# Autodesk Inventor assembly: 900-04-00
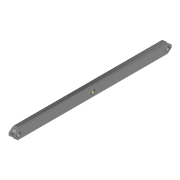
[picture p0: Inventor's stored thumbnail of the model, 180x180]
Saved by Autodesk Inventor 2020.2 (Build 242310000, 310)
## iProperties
Created: 2015-10
Part Number: 900-04-00
Document SubType Name: Konstrukcja spawana
Designer: F.Stasiak
Weld Material: Aluminium 6061, spawane
Mass: 21817.1 g
Surface Area: 11771.4 cm^2
Volume: 2908.78 cm^3
Density: 7.50043 g/cm^3
Catalog Web Link: www.expertbooks.pl
Manager: www.cadconsulting.pl
Company: Fabian Stasiak CAD Consulting
Author: F.Stasiak
Subject: Zbiór ćwiczeń. Autodesk Inventor 2020. Kurs Professional
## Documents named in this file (3)
- C:\2020_Kurs_Professional\R3 Dynamika\Komponenty_dyn\900-04-00.iam
- C:\2020_Kurs_Professional\R3 Dynamika\Komponenty_dyn\DIN 59 410 - 900-04-01.ipt
- C:\2020_Kurs_Professional\R3 Dynamika\Komponenty_dyn\900-03-02.ipt
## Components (4 placed, 2 different names)
1. DIN 59 410 - 900-04-01:1 — Zestawiający:1, Zestawiający:2, Zestawiający:3, Zestawiający:4, Zestawiający:5, Zestawiający:6
2. 900-03-02:1 — Zestawiający:1, Zestawiający:2, Zestawiający:8
3. 900-03-02:2 — Zestawiający:3, Zestawiający:4, Zestawiający:7, Zestawiający:8
4. 900-03-02:3 — Zestawiający:5, Zestawiający:6, Zestawiający:7
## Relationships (8: Mate 8)
- Zestawiający:1 [Mate]: DIN 59 410 - 900-04-01:1 ↔ 900-03-02:1
- Zestawiający:2 [Mate]: DIN 59 410 - 900-04-01:1 ↔ 900-03-02:1
- Zestawiający:3 [Mate]: DIN 59 410 - 900-04-01:1 ↔ 900-03-02:2
- Zestawiający:4 [Mate]: DIN 59 410 - 900-04-01:1 ↔ 900-03-02:2
- Zestawiający:5 [Mate]: DIN 59 410 - 900-04-01:1 ↔ 900-03-02:3
- Zestawiający:6 [Mate]: DIN 59 410 - 900-04-01:1 ↔ 900-03-02:3
- Zestawiający:7 [Mate]: 900-03-02:2 ↔ 900-03-02:3
- Zestawiający:8 [Mate]: 900-03-02:1 ↔ 900-03-02:2
